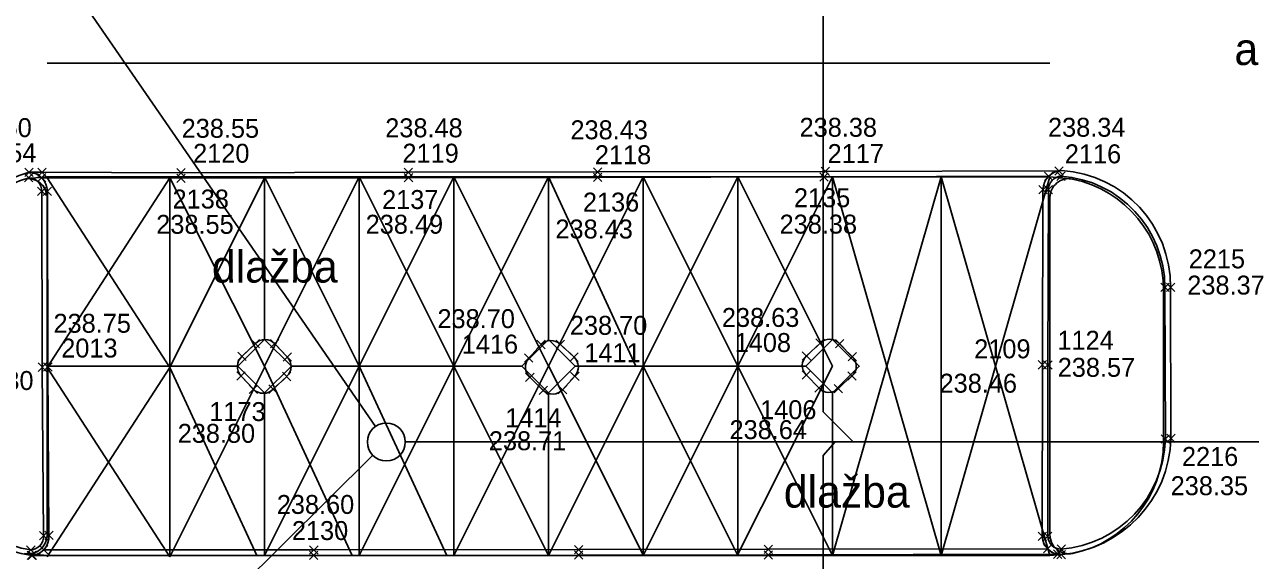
# Model space of a CAD drawing. Extents: x -264165 to -263733, y -1242319 to -1242245.
# Drawn here: x -263956.67 to -263924.28, y -1242287.11 to -1242272.97 of the extents above; entities that cross this region are included whole.
import ezdxf

# ---------------------------------------------------------------- set-up
doc = ezdxf.new("R2010")
doc.units = 0
for name, color, linetype in [('KFA_BOD_CISLO', 7, 'Continuous'), ('KFA_BOD_SYMBOL', 7, 'Continuous'), ('KFA_BOD_VYSKA', 7, 'Continuous'), ('KFA_SO_20-2_OBRUBNIKY_DOLNA_HRANA', 7, 'Continuous'), ('KFA_SO_20-2_OBRUBNIKY_HORNA_HRANA', 7, 'Continuous'), ('POPIS', 7, 'Continuous'), ('PROJEKT_OBRUBNIKY_KOMUNIKACIE', 7, 'Continuous'), ('PROJEKT_TDZ_VODOROVNE', 7, 'Continuous'), ('SITUACIA_DSP_2D', 7, 'Continuous')]:
    doc.layers.add(name, color=color, linetype=linetype)

msp = doc.modelspace()

# ---------------------------------------------------------------- linework, layer by layer
at = {"layer": 'KFA_BOD_SYMBOL'}
for p, q in [((-263956.664, -1242277.12), (-263956.443, -1242276.899)), ((-263956.443, -1242277.12), (-263956.664, -1242276.899)), ((-263956.658, -1242276.977), (-263956.437, -1242276.755)), ((-263956.437, -1242276.977), (-263956.658, -1242276.755)), ((-263956.321, -1242277.12), (-263956.1, -1242276.9)), ((-263956.1, -1242277.12), (-263956.321, -1242276.9)), ((-263956.313, -1242276.977), (-263956.092, -1242276.755)), ((-263956.092, -1242276.977), (-263956.313, -1242276.755)), ((-263952.644, -1242276.99), (-263952.424, -1242276.769)), ((-263952.424, -1242276.99), (-263952.644, -1242276.769)), ((-263952.639, -1242277.133), (-263952.418, -1242276.911)), ((-263952.418, -1242277.133), (-263952.639, -1242276.911)), ((-263946.639, -1242276.977), (-263946.418, -1242276.755)), ((-263946.418, -1242276.977), (-263946.639, -1242276.755)), ((-263946.634, -1242277.12), (-263946.413, -1242276.9)), ((-263946.413, -1242277.12), (-263946.634, -1242276.9)), ((-263941.639, -1242276.965), (-263941.417, -1242276.744)), ((-263941.417, -1242276.965), (-263941.639, -1242276.744)), ((-263941.638, -1242277.11), (-263941.416, -1242276.89)), ((-263941.416, -1242277.11), (-263941.638, -1242276.89)), ((-263935.656, -1242277.1), (-263935.435, -1242276.879)), ((-263935.435, -1242277.1), (-263935.656, -1242276.879)), ((-263935.626, -1242276.954), (-263935.405, -1242276.732)), ((-263935.405, -1242276.954), (-263935.626, -1242276.732)), ((-263929.725, -1242277.082), (-263929.503, -1242276.86)), ((-263929.503, -1242277.082), (-263929.725, -1242276.86)), ((-263929.453, -1242276.938), (-263929.231, -1242276.718)), ((-263929.231, -1242276.938), (-263929.453, -1242276.718)), ((-263929.395, -1242277.079), (-263929.174, -1242276.857)), ((-263929.174, -1242277.079), (-263929.395, -1242276.857)), ((-263929.875, -1242277.434), (-263929.654, -1242277.214)), ((-263929.654, -1242277.434), (-263929.875, -1242277.214)), ((-263929.731, -1242277.434), (-263929.51, -1242277.213)), ((-263929.51, -1242277.434), (-263929.731, -1242277.213)), ((-263956.319, -1242277.482), (-263956.098, -1242277.262)), ((-263956.098, -1242277.482), (-263956.319, -1242277.262)), ((-263956.172, -1242277.478), (-263955.951, -1242277.257)), ((-263955.951, -1242277.478), (-263956.172, -1242277.257)), ((-263926.653, -1242280.012), (-263926.432, -1242279.792)), ((-263926.432, -1242280.012), (-263926.653, -1242279.792)), ((-263926.504, -1242280.012), (-263926.283, -1242279.792)), ((-263926.283, -1242280.012), (-263926.504, -1242279.792)), ((-263950.677, -1242281.495), (-263950.456, -1242281.274)), ((-263950.456, -1242281.495), (-263950.677, -1242281.274)), ((-263950.171, -1242281.497), (-263949.95, -1242281.275)), ((-263949.95, -1242281.497), (-263950.171, -1242281.275)), ((-263943.131, -1242281.521), (-263942.91, -1242281.299)), ((-263942.91, -1242281.521), (-263943.131, -1242281.299)), ((-263942.622, -1242281.516), (-263942.401, -1242281.296)), ((-263942.401, -1242281.516), (-263942.622, -1242281.296)), ((-263935.762, -1242281.485), (-263935.541, -1242281.264)), ((-263935.541, -1242281.485), (-263935.762, -1242281.264)), ((-263935.247, -1242281.499), (-263935.025, -1242281.279)), ((-263935.025, -1242281.499), (-263935.247, -1242281.279)), ((-263951.035, -1242281.835), (-263950.814, -1242281.613)), ((-263950.814, -1242281.835), (-263951.035, -1242281.613)), ((-263949.835, -1242281.85), (-263949.614, -1242281.629)), ((-263949.614, -1242281.85), (-263949.835, -1242281.629)), ((-263943.458, -1242281.879), (-263943.236, -1242281.657)), ((-263943.236, -1242281.879), (-263943.458, -1242281.657)), ((-263942.261, -1242281.855), (-263942.04, -1242281.633)), ((-263942.04, -1242281.855), (-263942.261, -1242281.633)), ((-263936.122, -1242281.819), (-263935.9, -1242281.599)), ((-263935.9, -1242281.819), (-263936.122, -1242281.599)), ((-263934.91, -1242281.845), (-263934.689, -1242281.623)), ((-263934.689, -1242281.845), (-263934.91, -1242281.623)), ((-263956.308, -1242282.119), (-263956.087, -1242281.897)), ((-263956.087, -1242282.119), (-263956.308, -1242281.897)), ((-263956.16, -1242282.117), (-263955.938, -1242281.896)), ((-263955.938, -1242282.117), (-263956.16, -1242281.896)), ((-263936.128, -1242282.323), (-263935.906, -1242282.102)), ((-263935.906, -1242282.323), (-263936.128, -1242282.102)), ((-263929.889, -1242282.058), (-263929.668, -1242281.836)), ((-263929.668, -1242282.058), (-263929.889, -1242281.836)), ((-263929.746, -1242282.062), (-263929.524, -1242281.84)), ((-263929.524, -1242282.062), (-263929.746, -1242281.84)), ((-263951.06, -1242282.347), (-263950.839, -1242282.127)), ((-263950.839, -1242282.347), (-263951.06, -1242282.127)), ((-263949.851, -1242282.366), (-263949.63, -1242282.144)), ((-263949.63, -1242282.366), (-263949.851, -1242282.144)), ((-263943.429, -1242282.386), (-263943.208, -1242282.164)), ((-263943.208, -1242282.386), (-263943.429, -1242282.164)), ((-263942.241, -1242282.356), (-263942.019, -1242282.136)), ((-263942.019, -1242282.356), (-263942.241, -1242282.136)), ((-263934.92, -1242282.347), (-263934.698, -1242282.127)), ((-263934.698, -1242282.347), (-263934.92, -1242282.127)), ((-263950.729, -1242282.701), (-263950.508, -1242282.481)), ((-263950.508, -1242282.701), (-263950.729, -1242282.481)), ((-263950.209, -1242282.7), (-263949.987, -1242282.478)), ((-263949.987, -1242282.7), (-263950.209, -1242282.478)), ((-263943.073, -1242282.731), (-263942.852, -1242282.511)), ((-263942.852, -1242282.731), (-263943.073, -1242282.511)), ((-263942.566, -1242282.715), (-263942.345, -1242282.495)), ((-263942.345, -1242282.715), (-263942.566, -1242282.495)), ((-263935.791, -1242282.671), (-263935.569, -1242282.45)), ((-263935.569, -1242282.671), (-263935.791, -1242282.45)), ((-263935.283, -1242282.684), (-263935.062, -1242282.464)), ((-263935.062, -1242282.684), (-263935.283, -1242282.464)), ((-263926.639, -1242284.015), (-263926.418, -1242283.793)), ((-263926.418, -1242284.015), (-263926.639, -1242283.793)), ((-263926.493, -1242283.995), (-263926.272, -1242283.774)), ((-263926.272, -1242283.995), (-263926.493, -1242283.774)), ((-263956.274, -1242286.563), (-263956.052, -1242286.343)), ((-263956.052, -1242286.563), (-263956.274, -1242286.343)), ((-263956.132, -1242286.559), (-263955.91, -1242286.339)), ((-263955.91, -1242286.559), (-263956.132, -1242286.339)), ((-263929.894, -1242286.586), (-263929.672, -1242286.365)), ((-263929.672, -1242286.586), (-263929.894, -1242286.365)), ((-263929.747, -1242286.585), (-263929.526, -1242286.363)), ((-263929.526, -1242286.585), (-263929.747, -1242286.363)), ((-263956.609, -1242286.941), (-263956.388, -1242286.721)), ((-263956.388, -1242286.941), (-263956.609, -1242286.721)), ((-263956.592, -1242287.088), (-263956.371, -1242286.867)), ((-263956.371, -1242287.088), (-263956.592, -1242286.867)), ((-263956.569, -1242287.086), (-263956.348, -1242286.865)), ((-263956.348, -1242287.086), (-263956.569, -1242286.865)), ((-263956.272, -1242286.938), (-263956.051, -1242286.718)), ((-263956.051, -1242286.938), (-263956.272, -1242286.718)), ((-263949.139, -1242287.088), (-263948.917, -1242286.867)), ((-263948.917, -1242287.088), (-263949.139, -1242286.867)), ((-263949.134, -1242286.943), (-263948.913, -1242286.721)), ((-263948.913, -1242286.943), (-263949.134, -1242286.721)), ((-263942.136, -1242286.934), (-263941.915, -1242286.714)), ((-263941.915, -1242286.934), (-263942.136, -1242286.714)), ((-263942.136, -1242287.078), (-263941.915, -1242286.856)), ((-263941.915, -1242287.078), (-263942.136, -1242286.856)), ((-263937.132, -1242286.926), (-263936.91, -1242286.704)), ((-263936.91, -1242286.926), (-263937.132, -1242286.704)), ((-263937.128, -1242287.073), (-263936.907, -1242286.852)), ((-263936.907, -1242287.073), (-263937.128, -1242286.852)), ((-263929.753, -1242286.911), (-263929.532, -1242286.691)), ((-263929.532, -1242286.911), (-263929.753, -1242286.691)), ((-263929.486, -1242287.055), (-263929.265, -1242286.833)), ((-263929.265, -1242287.055), (-263929.486, -1242286.833)), ((-263929.394, -1242287.063), (-263929.172, -1242286.843)), ((-263929.172, -1242287.063), (-263929.394, -1242286.843)), ((-263929.391, -1242286.923), (-263929.17, -1242286.701)), ((-263929.17, -1242286.923), (-263929.391, -1242286.701))]:
    msp.add_line(p, q, dxfattribs=at)
at = {"layer": 'KFA_SO_20-2_OBRUBNIKY_DOLNA_HRANA'}
for p, q in [((-263956.203, -1242276.866), (-263956.547, -1242276.866)), ((-263929.779, -1242281.947), (-263929.764, -1242277.324)), ((-263926.394, -1242279.902), (-263926.383, -1242283.884)), ((-263956.049, -1242282.006), (-263956.021, -1242286.449))]:
    msp.add_line(p, q, dxfattribs=at)
for points in [[(-263929.342, -1242276.828), (-263935.515, -1242276.843), (-263941.528, -1242276.854), (-263946.529, -1242276.866), (-263952.534, -1242276.879), (-263956.203, -1242276.866)], [(-263929.614, -1242276.971), (-263935.546, -1242276.989), (-263941.527, -1242277), (-263946.524, -1242277.01), (-263952.529, -1242277.022), (-263956.21, -1242277.01)], [(-263956.049, -1242282.006), (-263956.062, -1242277.367)], [(-263929.779, -1242281.947), (-263929.783, -1242286.475)], [(-263956.459, -1242286.975), (-263949.028, -1242286.977), (-263942.025, -1242286.967), (-263937.018, -1242286.962), (-263929.376, -1242286.944)], [(-263956.161, -1242286.828), (-263949.024, -1242286.832), (-263942.025, -1242286.824), (-263937.021, -1242286.815), (-263929.643, -1242286.801)]]:
    msp.add_lwpolyline(points, dxfattribs=at)
for centre, major_axis, ratio, start_param, end_param in [((-263955.655, -1242280.15), (-0.469, 3.371), 0.999366, 0.126889, 1.396912), ((-263956.561, -1242277.364), (0.392, -0.308), 0.999776, 0.660695, 2.208885), ((-263929.251, -1242277.333), (-0.225, -0.461), 0.999518, 3.628083, 5.148577), ((-263929.454, -1242279.874), (-2.794, 1.247), 0.999926, 3.552159, 5.071087), ((-263956.094, -1242284.026), (2.785, -1.049), 0.999986, 3.498387, 4.942262), ((-263929.543, -1242283.803), (-1.849, -2.564), 0.999588, 0.707227, 2.169601), ((-263956.517, -1242286.481), (-0.325, 0.376), 0.999896, 2.501525, 4.065147), ((-263929.284, -1242286.454), (-0.498, 0.04), 0.999243, 0.122557, 1.651969)]:
    msp.add_ellipse(centre, major_axis=major_axis, ratio=ratio, start_param=start_param, end_param=end_param, dxfattribs=at)
at = {"layer": 'KFA_SO_20-2_OBRUBNIKY_HORNA_HRANA'}
for p, q in [((-263929.621, -1242277.323), (-263929.635, -1242281.951)), ((-263926.542, -1242279.902), (-263926.529, -1242283.904)), ((-263950.925, -1242281.724), (-263950.567, -1242281.384)), ((-263950.061, -1242281.386), (-263949.725, -1242281.739)), ((-263943.347, -1242281.768), (-263943.02, -1242281.41)), ((-263942.512, -1242281.406), (-263942.15, -1242281.744)), ((-263936.011, -1242281.709), (-263935.651, -1242281.374)), ((-263935.136, -1242281.389), (-263934.8, -1242281.734)), ((-263956.163, -1242286.453), (-263956.198, -1242282.008)), ((-263950.618, -1242282.591), (-263950.949, -1242282.237)), ((-263949.741, -1242282.255), (-263950.098, -1242282.589)), ((-263942.963, -1242282.621), (-263943.318, -1242282.275)), ((-263942.13, -1242282.246), (-263942.455, -1242282.605)), ((-263935.68, -1242282.56), (-263936.017, -1242282.212)), ((-263934.809, -1242282.237), (-263935.172, -1242282.574))]:
    msp.add_line(p, q, dxfattribs=at)
for points in [[(-263956.198, -1242282.008), (-263956.209, -1242277.372)], [(-263929.635, -1242281.951), (-263929.637, -1242286.474)]]:
    msp.add_lwpolyline(points, dxfattribs=at)
msp.add_arc((-263956.562, -1242277.362), 0.354, 358.4428, 88.4784, dxfattribs=at)
for centre, major_axis, ratio, start_param, end_param in [((-263955.636, -1242280.153), (0.058, 3.275), 0.999165, 0.301718, 1.55091), ((-263929.267, -1242277.322), (-0.179, -0.305), 0.99963, 3.722909, 5.246916), ((-263929.493, -1242279.912), (-1.33, 2.635), 0.999911, 4.248389, 5.745248), ((-263950.315, -1242281.634), (-0.013, 0.355), 0.99993, 5.447992, 7.035043), ((-263942.764, -1242281.666), (-0.233, -0.278), 0.99997, 3.069511, 4.623871), ((-263935.401, -1242281.63), (-0.358, 0.01), 0.999622, 3.908462, 5.516316), ((-263950.683, -1242281.992), (0.125, -0.339), 0.999689, 3.522099, 5.100812), ((-263949.985, -1242281.989), (0.36, 0.022), 0.999953, 5.392805, 6.987909), ((-263943.076, -1242282.007), (0.094, -0.349), 0.99925, 3.728899, 5.286258), ((-263942.392, -1242282.005), (-0.351, 0.057), 0.999794, 2.559372, 4.127429), ((-263935.772, -1242281.963), (0.245, -0.249), 0.999808, 3.117958, 4.726731), ((-263935.037, -1242281.981), (0.292, 0.18), 0.999599, 4.889089, 6.538219), ((-263950.359, -1242282.333), (0.255, -0.262), 0.999711, 4.72531, 6.306501), ((-263942.717, -1242282.37), (0.351, 0.011), 0.99932, 3.904538, 5.52024), ((-263935.419, -1242282.322), (0.352, -0.026), 0.999116, 3.955307, 5.56313), ((-263956.072, -1242284.009), (-2.548, 1.287), 0.999996, 0.470217, 1.888537), ((-263929.525, -1242283.825), (-1.543, -2.57), 0.999644, 0.62249, 2.084881), ((-263956.518, -1242286.476), (0.352, -0.051), 0.999899, 4.911695, 6.49199), ((-263929.285, -1242286.46), (-0.352, 0.011), 0.999433, 0.071166, 1.617679)]:
    msp.add_ellipse(centre, major_axis=major_axis, ratio=ratio, start_param=start_param, end_param=end_param, dxfattribs=at)
at = {"layer": 'PROJEKT_OBRUBNIKY_KOMUNIKACIE'}
for p, q in [((-263956.58, -1242277.033), (-263956.668, -1242277.043)), ((-263956.492, -1242277.039), (-263956.58, -1242277.033)), ((-263956.068, -1242276.982), (-263956.568, -1242277.033)), ((-263956.406, -1242277.06), (-263956.492, -1242277.039)), ((-263956.325, -1242277.096), (-263956.406, -1242277.06)), ((-263956.252, -1242277.145), (-263956.325, -1242277.096)), ((-263956.188, -1242277.207), (-263956.252, -1242277.145)), ((-263956.137, -1242277.279), (-263956.188, -1242277.207)), ((-263929.58, -1242276.982), (-263956.068, -1242276.982)), ((-263929.58, -1242276.982), (-263928.98, -1242277.043)), ((-263956.099, -1242277.359), (-263956.137, -1242277.279)), ((-263956.076, -1242277.445), (-263956.099, -1242277.359)), ((-263956.068, -1242277.533), (-263956.076, -1242277.445)), ((-263956.068, -1242286.432), (-263956.068, -1242277.533)), ((-263929.58, -1242286.432), (-263929.58, -1242277.533)), ((-263926.58, -1242283.982), (-263926.58, -1242279.982)), ((-263926.58, -1242280.482), (-263926.58, -1242283.982)), ((-263956.137, -1242286.685), (-263956.099, -1242286.605)), ((-263956.099, -1242286.605), (-263956.076, -1242286.52)), ((-263956.076, -1242286.52), (-263956.068, -1242286.432)), ((-263956.668, -1242286.922), (-263956.58, -1242286.932)), ((-263956.068, -1242286.982), (-263956.616, -1242286.929)), ((-263956.58, -1242286.932), (-263956.492, -1242286.926)), ((-263956.492, -1242286.926), (-263956.406, -1242286.905)), ((-263956.406, -1242286.905), (-263956.325, -1242286.869)), ((-263956.325, -1242286.869), (-263956.252, -1242286.819)), ((-263956.252, -1242286.819), (-263956.188, -1242286.757)), ((-263956.188, -1242286.757), (-263956.137, -1242286.685)), ((-263929.58, -1242286.982), (-263928.98, -1242286.922)), ((-263929.58, -1242286.982), (-263956.068, -1242286.982))]:
    msp.add_line(p, q, dxfattribs=at)
for points in [[(-263950.324, -1242281.275), (-263949.617, -1242281.982), (-263950.324, -1242282.689), (-263951.031, -1242281.982), (-263950.324, -1242281.275)], [(-263942.824, -1242281.275), (-263942.117, -1242281.982), (-263942.824, -1242282.689), (-263943.531, -1242281.982), (-263942.824, -1242281.275)], [(-263935.324, -1242281.275), (-263934.617, -1242281.982), (-263935.324, -1242282.689), (-263936.031, -1242281.982), (-263935.324, -1242281.275)]]:
    msp.add_lwpolyline(points, dxfattribs=at)
for centre, radius, start, end in [((-263929.08, -1242277.533), 0.5, 78.463, 180), ((-263929.58, -1242279.982), 3, 0, 78.463), ((-263929.58, -1242283.982), 3, 281.537, 0), ((-263929.08, -1242286.432), 0.5, 180, 281.537)]:
    msp.add_arc(centre, radius, start, end, dxfattribs=at)
at = {"layer": 'PROJEKT_TDZ_VODOROVNE'}
for p, q in [((-263929.58, -1242273.982), (-263956.068, -1242273.982)), ((-263956.068, -1242282.014), (-263952.824, -1242277.014)), ((-263956.068, -1242277.014), (-263952.824, -1242282.014)), ((-263952.824, -1242281.982), (-263952.824, -1242276.982)), ((-263952.824, -1242277.014), (-263950.324, -1242281.982)), ((-263952.824, -1242282.014), (-263950.324, -1242277.014)), ((-263950.324, -1242281.275), (-263950.324, -1242276.982)), ((-263950.324, -1242276.982), (-263947.824, -1242281.982)), ((-263950.324, -1242281.982), (-263947.824, -1242276.982)), ((-263947.824, -1242281.982), (-263947.824, -1242276.982)), ((-263947.824, -1242276.982), (-263945.324, -1242281.982)), ((-263947.824, -1242281.982), (-263945.324, -1242276.982)), ((-263945.324, -1242281.982), (-263945.324, -1242276.982)), ((-263945.324, -1242276.982), (-263942.824, -1242281.982)), ((-263945.324, -1242281.982), (-263942.824, -1242276.982)), ((-263942.824, -1242281.275), (-263942.824, -1242276.982)), ((-263942.824, -1242276.982), (-263940.514, -1242281.982)), ((-263942.824, -1242281.982), (-263940.324, -1242276.982)), ((-263940.324, -1242281.982), (-263940.324, -1242276.982)), ((-263940.324, -1242276.982), (-263937.824, -1242281.982)), ((-263940.324, -1242281.982), (-263937.824, -1242276.982)), ((-263937.824, -1242281.982), (-263937.824, -1242276.982)), ((-263937.824, -1242276.982), (-263935.324, -1242281.982)), ((-263937.824, -1242281.982), (-263935.324, -1242276.982)), ((-263935.324, -1242281.275), (-263935.324, -1242276.982)), ((-263935.324, -1242276.982), (-263932.452, -1242286.982)), ((-263935.324, -1242286.982), (-263932.452, -1242276.982)), ((-263932.452, -1242281.982), (-263932.452, -1242276.982)), ((-263932.452, -1242276.982), (-263929.58, -1242286.982)), ((-263932.452, -1242286.982), (-263929.58, -1242276.982)), ((-263951.031, -1242281.982), (-263956.068, -1242281.982)), ((-263956.068, -1242287.014), (-263952.824, -1242282.014)), ((-263956.068, -1242282.014), (-263952.824, -1242287.014)), ((-263952.824, -1242281.982), (-263952.824, -1242286.982)), ((-263952.824, -1242282.014), (-263950.529, -1242286.982)), ((-263952.824, -1242287.014), (-263950.324, -1242282.014)), ((-263950.324, -1242281.982), (-263948.014, -1242286.982)), ((-263950.324, -1242286.982), (-263947.824, -1242281.982)), ((-263943.531, -1242281.982), (-263949.617, -1242281.982)), ((-263947.824, -1242281.982), (-263947.824, -1242286.982)), ((-263947.824, -1242281.982), (-263945.514, -1242286.982)), ((-263947.824, -1242286.982), (-263945.324, -1242281.982)), ((-263945.324, -1242281.982), (-263945.324, -1242286.982)), ((-263945.324, -1242286.982), (-263942.824, -1242281.982)), ((-263945.324, -1242281.982), (-263942.824, -1242286.982)), ((-263942.824, -1242281.967), (-263940.324, -1242286.967)), ((-263942.824, -1242286.982), (-263940.324, -1242281.982)), ((-263936.031, -1242281.982), (-263942.117, -1242281.982)), ((-263940.324, -1242281.982), (-263940.324, -1242286.982)), ((-263940.324, -1242286.982), (-263937.824, -1242281.982)), ((-263940.324, -1242281.982), (-263937.824, -1242286.982)), ((-263937.824, -1242281.982), (-263937.824, -1242286.982)), ((-263937.824, -1242281.982), (-263935.324, -1242286.982)), ((-263937.824, -1242286.943), (-263935.324, -1242281.982)), ((-263932.452, -1242281.982), (-263932.452, -1242286.982)), ((-263950.324, -1242282.689), (-263950.324, -1242286.982)), ((-263942.824, -1242282.689), (-263942.824, -1242286.982)), ((-263935.324, -1242282.689), (-263935.324, -1242286.982)), ((-263937.824, -1242286.079), (-263937.824, -1242286.943))]:
    msp.add_line(p, q, dxfattribs=at)
at = {"layer": 'SITUACIA_DSP_2D'}
for p, q in [((-263955.761, -1242271.455), (-263947.392, -1242283.571)), ((-263935.574, -1242271.473), (-263935.574, -1242283.187)), ((-263956.068, -1242286.432), (-263956.068, -1242277.533)), ((-263929.58, -1242286.432), (-263929.58, -1242277.533)), ((-263926.58, -1242283.982), (-263926.58, -1242279.982)), ((-263926.58, -1242280.482), (-263926.58, -1242283.982)), ((-263935.574, -1242283.187), (-263934.779, -1242283.982)), ((-263946.608, -1242283.982), (-263908.955, -1242283.982)), ((-263946.608, -1242283.982), (-263904.413, -1242283.982)), ((-263935.574, -1242284.343), (-263935.249, -1242283.982)), ((-263955.747, -1242292.522), (-263947.464, -1242284.334)), ((-263935.574, -1242292.492), (-263935.574, -1242284.343))]:
    msp.add_line(p, q, dxfattribs=at)
for points in [[(-263950.324, -1242281.275), (-263949.617, -1242281.982), (-263950.324, -1242282.689), (-263951.031, -1242281.982)], [(-263942.824, -1242281.275), (-263942.117, -1242281.982), (-263942.824, -1242282.689), (-263943.531, -1242281.982)], [(-263935.324, -1242281.275), (-263934.617, -1242281.982), (-263935.324, -1242282.689), (-263936.031, -1242281.982)]]:
    msp.add_lwpolyline(points, close=True, dxfattribs=at)
msp.add_circle((-263947.108, -1242283.982), 0.5, dxfattribs=at)
for centre, radius, start, end in [((-263956.568, -1242277.533), 0.5, 0, 101.537), ((-263929.08, -1242277.533), 0.5, 78.463, 180), ((-263929.58, -1242279.982), 3, 0, 78.463), ((-263929.58, -1242283.982), 3, 281.537, 0), ((-263956.568, -1242286.432), 0.5, 258.463, 0), ((-263929.08, -1242286.432), 0.5, 180, 281.537)]:
    msp.add_arc(centre, radius, start, end, dxfattribs=at)

# ---------------------------------------------------------------- texts
at = {"layer": 'KFA_BOD_CISLO'}
for s, p in [('2154', (-263957.84, -1242276.603)), ('2120', (-263952.212, -1242276.613)), ('2119', (-263946.683, -1242276.611)), ('2118', (-263941.6, -1242276.652)), ('2117', (-263935.452, -1242276.621)), ('2116', (-263929.186, -1242276.628)), ('2138', (-263952.755, -1242277.822)), ('2137', (-263947.221, -1242277.834)), ('2136', (-263941.916, -1242277.902)), ('2135', (-263936.342, -1242277.787)), ('2215', (-263925.914, -1242279.4)), ('1408', (-263937.907, -1242281.608)), ('1124', (-263929.382, -1242281.548)), ('2013', (-263955.696, -1242281.754)), ('1416', (-263945.116, -1242281.649)), ('1411', (-263941.878, -1242281.877)), ('2109', (-263931.58, -1242281.774)), ('1030', (-263957.915, -1242282.61)), ('1173', (-263951.785, -1242283.43)), ('1406', (-263937.235, -1242283.381)), ('1414', (-263943.968, -1242283.594)), ('2216', (-263926.093, -1242284.615)), ('2130', (-263949.603, -1242286.57))]:
    msp.add_text(s, height=0.5, dxfattribs=at).set_placement(p)
at = {"layer": 'KFA_BOD_VYSKA'}
for s, p in [('238.60', (-263958.519, -1242275.936)), ('238.55', (-263952.515, -1242275.955)), ('238.48', (-263947.137, -1242275.942)), ('238.43', (-263942.245, -1242275.994)), ('238.38', (-263936.193, -1242275.928)), ('238.34', (-263929.631, -1242275.927)), ('238.55', (-263953.186, -1242278.489)), ('238.49', (-263947.654, -1242278.486)), ('238.43', (-263942.642, -1242278.612)), ('238.38', (-263936.72, -1242278.483)), ('238.37', (-263925.952, -1242280.092)), ('238.70', (-263945.758, -1242280.978)), ('238.63', (-263938.245, -1242280.946)), ('238.75', (-263955.9, -1242281.1)), ('238.70', (-263942.261, -1242281.154)), ('238.57', (-263929.374, -1242282.263)), ('238.46', (-263932.495, -1242282.681)), ('238.64', (-263938.043, -1242283.906)), ('238.80', (-263952.619, -1242284.004)), ('238.71', (-263944.4, -1242284.2)), ('238.35', (-263926.391, -1242285.387)), ('238.60', (-263950.002, -1242285.881))]:
    msp.add_text(s, height=0.5, dxfattribs=at).set_placement(p)
at = {"layer": 'POPIS'}
for s, p in [('asfalt', (-263924.707, -1242274.034)), ('dlažba', (-263951.715, -1242279.775)), ('dlažba', (-263936.609, -1242285.714))]:
    msp.add_text(s, height=0.8438, dxfattribs=at).set_placement(p)

doc.saveas('drawing.dxf')
